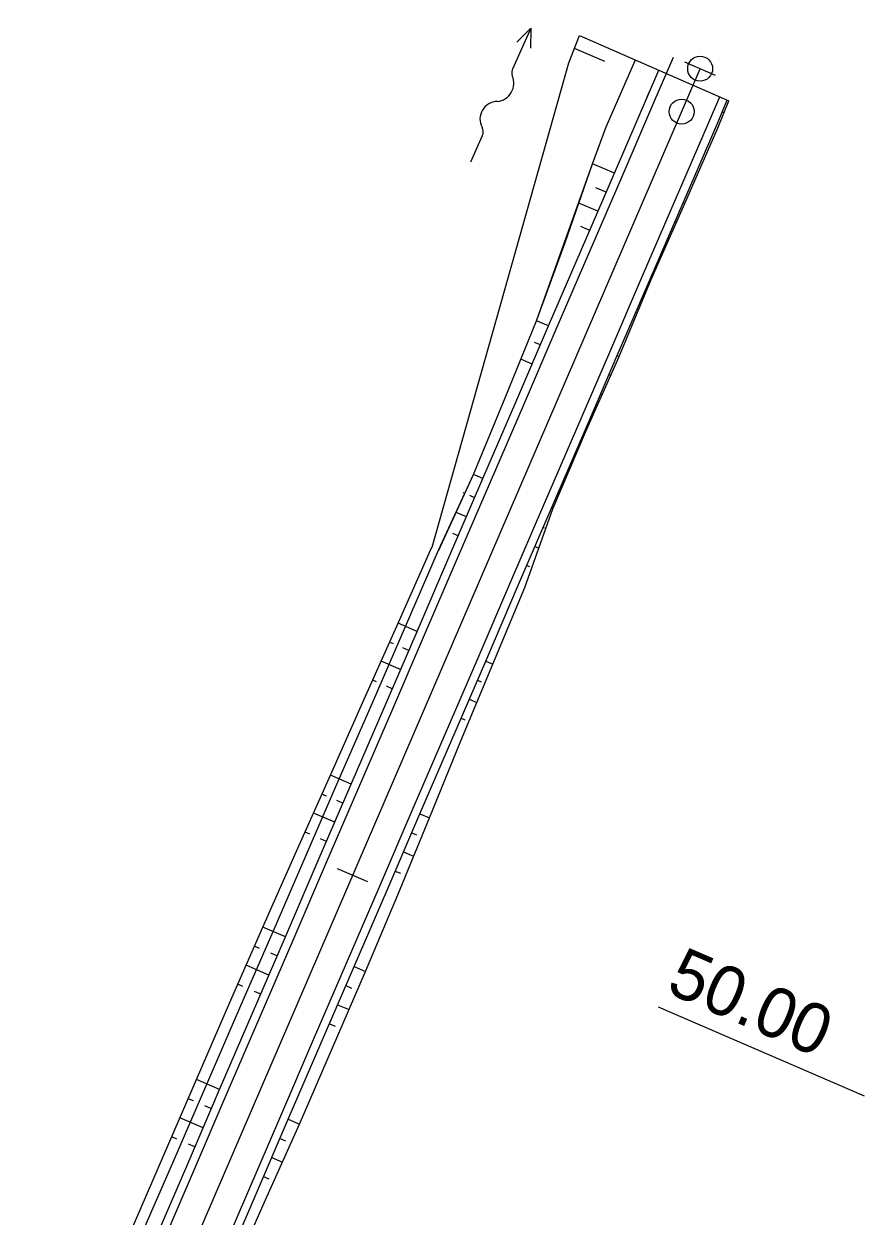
# Model space of a CAD drawing. Extents: x -481656 to -478728, y -1113199 to -1110710.
# Drawn here: x -480117.1 to -480066.6, y -1112436.3 to -1112364.6 of the extents above; entities that cross this region are included whole.
import ezdxf

# ---------------------------------------------------------------- set-up
doc = ezdxf.new("R2010")
doc.units = 0
for name, color, linetype in [('C14_HATCH_SLOPE_L', 7, 'Continuous'), ('C14_HATCH_SLOPE_R', 7, 'Continuous'), ('C14_HECTOMETRY', 7, 'Continuous'), ('C14_HLBODY', 7, 'Continuous'), ('C14_HRANA_TELESO', 7, 'Continuous'), ('C14_KORUNA', 7, 'Continuous'), ('C14_OSA', 7, 'Continuous'), ('C14_PRIKOP', 7, 'Continuous'), ('C14_STANICENI', 7, 'Continuous'), ('C14_VOZOVKA', 7, 'Continuous'), ('C14_ZPEVKRAJ', 7, 'Continuous'), ('DRENÁŽ', 7, 'Continuous'), ('PLYN', 7, 'Continuous')]:
    doc.layers.add(name, color=color, linetype=linetype)

# ---------------------------------------------------------------- blocks, each defined once
blk = doc.blocks.new('A$C70B')
at = {"layer": 'DRENÁŽ'}
for p, q in [((0.869, 0.002), (-0.869, -0.002)), ((6.861, 0.426), (7.971, -0.002)), ((7.971, -0.002), (5.275, -0.002)), ((7.971, -0.002), (6.862, -0.478))]:
    blk.add_line(p, q, dxfattribs=at)
for centre, radius, start, end in [((0.872, 0.584), 0.582, 269.69241, 322.79009), ((2.168, -0.416), 1.055, 24.40393, 142.08362), ((4.08, 0.589), 1.109, 210.88731, 317.37071), ((5.319, -0.636), 0.636, 85.97658, 131.72478)]:
    blk.add_arc(centre, radius, start, end, dxfattribs=at)

msp = doc.modelspace()

# ---------------------------------------------------------------- linework, layer by layer
at = {"layer": 'C14_HATCH_SLOPE_L'}
for p, q in [((-480082.17, -1112366.882), (-480084.006, -1112366.091)), ((-480082.169, -1112366.882), (-480084.005, -1112366.091)), ((-480081.597, -1112373.59), (-480082.906, -1112373.026)), ((-480083.321, -1112374.208), (-480083.321, -1112374.208)), ((-480082.091, -1112374.738), (-480082.706, -1112374.473)), ((-480082.586, -1112375.886), (-480083.735, -1112375.391)), ((-480084.15, -1112376.574), (-480084.15, -1112376.574)), ((-480083.081, -1112377.034), (-480083.616, -1112376.804)), ((-480085.554, -1112382.774), (-480086.281, -1112382.461)), ((-480086.751, -1112383.619), (-480086.751, -1112383.619)), ((-480086.049, -1112383.922), (-480086.4, -1112383.77)), ((-480086.544, -1112385.07), (-480087.222, -1112384.778)), ((-480089.512, -1112391.957), (-480090.068, -1112391.718)), ((-480090.644, -1112392.83), (-480090.694, -1112392.809)), ((-480090.007, -1112393.105), (-480090.301, -1112392.978)), ((-480090.501, -1112394.253), (-480091.12, -1112393.987)), ((-480090.996, -1112395.401), (-480091.321, -1112395.261)), ((-480093.469, -1112401.141), (-480094.609, -1112400.65)), ((-480094.889, -1112401.89), (-480095.117, -1112401.792)), ((-480093.964, -1112402.289), (-480094.312, -1112402.139)), ((-480094.459, -1112403.437), (-480095.626, -1112402.934)), ((-480095.896, -1112404.179), (-480096.134, -1112404.076)), ((-480094.954, -1112404.585), (-480095.306, -1112404.434)), ((-480097.427, -1112410.324), (-480098.678, -1112409.785)), ((-480098.915, -1112411.044), (-480099.187, -1112410.927)), ((-480097.922, -1112411.472), (-480098.282, -1112411.317)), ((-480098.416, -1112412.62), (-480099.695, -1112412.069)), ((-480099.921, -1112413.333), (-480100.203, -1112413.211)), ((-480098.911, -1112413.768), (-480099.275, -1112413.612)), ((-480101.385, -1112419.508), (-480102.746, -1112418.921)), ((-480102.937, -1112420.2), (-480103.249, -1112420.066)), ((-480101.879, -1112420.656), (-480102.252, -1112420.496)), ((-480102.374, -1112421.804), (-480103.751, -1112421.21)), ((-480103.938, -1112422.492), (-480104.254, -1112422.355)), ((-480102.869, -1112422.952), (-480103.245, -1112422.79)), ((-480105.342, -1112428.692), (-480106.733, -1112428.092)), ((-480106.918, -1112429.374), (-480107.229, -1112429.239)), ((-480105.837, -1112429.839), (-480106.222, -1112429.674)), ((-480106.332, -1112430.987), (-480107.726, -1112430.387)), ((-480107.912, -1112431.668), (-480108.222, -1112431.534)), ((-480106.826, -1112432.135), (-480107.214, -1112431.968))]:
    msp.add_line(p, q, dxfattribs=at)
at = {"layer": 'C14_HATCH_SLOPE_R'}
for p, q in [((-480075.116, -1112369.922), (-480075.06, -1112369.946)), ((-480075.004, -1112369.971), (-480075.004, -1112369.971)), ((-480077.464, -1112375.371), (-480077.359, -1112375.417)), ((-480077.959, -1112376.519), (-480077.913, -1112376.539)), ((-480077.867, -1112376.559), (-480077.867, -1112376.559)), ((-480078.453, -1112377.667), (-480078.376, -1112377.701)), ((-480078.948, -1112378.815), (-480078.916, -1112378.829)), ((-480078.884, -1112378.843), (-480078.884, -1112378.843)), ((-480081.422, -1112384.555), (-480081.303, -1112384.606)), ((-480081.916, -1112385.703), (-480081.864, -1112385.725)), ((-480081.813, -1112385.747), (-480081.813, -1112385.747)), ((-480082.411, -1112386.851), (-480082.323, -1112386.888)), ((-480082.906, -1112387.999), (-480082.87, -1112388.014)), ((-480082.834, -1112388.03), (-480082.834, -1112388.03)), ((-480085.379, -1112393.738), (-480085.299, -1112393.773)), ((-480085.874, -1112394.886), (-480085.797, -1112394.92)), ((-480085.72, -1112394.953), (-480085.72, -1112394.953)), ((-480086.369, -1112396.034), (-480086.14, -1112396.133)), ((-480086.863, -1112397.182), (-480086.712, -1112397.248)), ((-480086.561, -1112397.313), (-480086.561, -1112397.313)), ((-480089.337, -1112402.922), (-480088.911, -1112403.106)), ((-480089.832, -1112404.07), (-480089.612, -1112404.165)), ((-480089.391, -1112404.26), (-480089.391, -1112404.26)), ((-480090.326, -1112405.218), (-480089.871, -1112405.414)), ((-480090.821, -1112406.366), (-480090.586, -1112406.467)), ((-480090.351, -1112406.568), (-480090.351, -1112406.568)), ((-480093.294, -1112412.105), (-480092.728, -1112412.35)), ((-480093.789, -1112413.253), (-480093.495, -1112413.38)), ((-480093.202, -1112413.506), (-480093.202, -1112413.506)), ((-480094.284, -1112414.401), (-480093.677, -1112414.663)), ((-480094.779, -1112415.549), (-480094.465, -1112415.684)), ((-480094.151, -1112415.82), (-480094.151, -1112415.82)), ((-480097.252, -1112421.289), (-480096.567, -1112421.584)), ((-480097.747, -1112422.437), (-480097.404, -1112422.584)), ((-480097.061, -1112422.732), (-480097.061, -1112422.732)), ((-480098.242, -1112423.585), (-480097.555, -1112423.881)), ((-480098.736, -1112424.733), (-480098.392, -1112424.881)), ((-480098.049, -1112425.029), (-480098.049, -1112425.029)), ((-480101.21, -1112430.472), (-480100.542, -1112430.76)), ((-480101.704, -1112431.62), (-480101.378, -1112431.761)), ((-480101.052, -1112431.902), (-480101.052, -1112431.902)), ((-480102.199, -1112432.768), (-480101.562, -1112433.043)), ((-480102.694, -1112433.916), (-480102.383, -1112434.05)), ((-480102.072, -1112434.184), (-480102.072, -1112434.184))]:
    msp.add_line(p, q, dxfattribs=at)
at = {"layer": 'C14_HECTOMETRY'}
msp.add_circle((-480077.551, -1112369.889), 0.75, dxfattribs=at)
at = {"layer": 'C14_HLBODY'}
msp.add_circle((-480076.44, -1112367.31), 0.75, dxfattribs=at)
at = {"layer": 'C14_HRANA_TELESO'}
for p, q in [((-480084.346, -1112366.961), (-480083.701, -1112365.308)), ((-480084.345, -1112366.962), (-480083.7, -1112365.308)), ((-480083.7, -1112365.308), (-480074.708, -1112369.248)), ((-480092.564, -1112396.087), (-480084.345, -1112366.962)), ((-480075.357, -1112370.835), (-480074.708, -1112369.248)), ((-480077.359, -1112375.417), (-480075.357, -1112370.835)), ((-480086.281, -1112382.461), (-480082.906, -1112373.026)), ((-480084.564, -1112377.756), (-480082.906, -1112373.026)), ((-480079.392, -1112379.985), (-480077.359, -1112375.417)), ((-480086.281, -1112382.461), (-480084.564, -1112377.756)), ((-480081.303, -1112384.606), (-480079.392, -1112379.985)), ((-480088.162, -1112387.095), (-480086.281, -1112382.461)), ((-480088.162, -1112387.095), (-480086.281, -1112382.461)), ((-480083.344, -1112389.171), (-480081.303, -1112384.606)), ((-480090.068, -1112391.718), (-480088.162, -1112387.095)), ((-480090.068, -1112391.718), (-480088.162, -1112387.095)), ((-480085.299, -1112393.773), (-480083.344, -1112389.171)), ((-480086.981, -1112398.493), (-480085.299, -1112393.773)), ((-480094.609, -1112400.65), (-480092.575, -1112396.082)), ((-480088.911, -1112403.106), (-480086.981, -1112398.493)), ((-480096.643, -1112405.218), (-480094.609, -1112400.65)), ((-480090.832, -1112407.722), (-480088.911, -1112403.106)), ((-480098.678, -1112409.785), (-480096.643, -1112405.218)), ((-480092.728, -1112412.35), (-480090.832, -1112407.722)), ((-480100.712, -1112414.354), (-480098.678, -1112409.785)), ((-480094.625, -1112416.976), (-480092.728, -1112412.35)), ((-480102.746, -1112418.921), (-480100.712, -1112414.354)), ((-480096.567, -1112421.584), (-480094.625, -1112416.976)), ((-480104.756, -1112423.499), (-480102.746, -1112418.921)), ((-480098.543, -1112426.177), (-480096.567, -1112421.584)), ((-480106.733, -1112428.092), (-480104.756, -1112423.499)), ((-480100.542, -1112430.76), (-480098.543, -1112426.177)), ((-480108.719, -1112432.681), (-480106.733, -1112428.092)), ((-480102.582, -1112435.326), (-480100.542, -1112430.76)), ((-480110.705, -1112437.27), (-480108.719, -1112432.681)), ((-480104.622, -1112439.891), (-480102.582, -1112435.326))]:
    msp.add_line(p, q, dxfattribs=at)
at = {"layer": 'C14_KORUNA'}
for p, q in [((-480081.597, -1112373.59), (-480078.928, -1112367.399)), ((-480079.618, -1112368.999), (-480079.486, -1112368.692)), ((-480075.485, -1112370.78), (-480074.806, -1112369.204)), ((-480077.464, -1112375.371), (-480075.485, -1112370.78)), ((-480083.575, -1112378.182), (-480081.597, -1112373.59)), ((-480079.443, -1112379.963), (-480077.464, -1112375.371)), ((-480085.554, -1112382.774), (-480083.575, -1112378.182)), ((-480081.422, -1112384.555), (-480079.443, -1112379.963)), ((-480087.533, -1112387.366), (-480085.554, -1112382.774)), ((-480083.4, -1112389.147), (-480081.422, -1112384.555)), ((-480089.512, -1112391.957), (-480087.533, -1112387.366)), ((-480085.379, -1112393.738), (-480083.4, -1112389.147)), ((-480091.491, -1112396.549), (-480089.512, -1112391.957)), ((-480087.358, -1112398.33), (-480085.379, -1112393.738)), ((-480093.469, -1112401.141), (-480091.491, -1112396.549)), ((-480089.337, -1112402.922), (-480087.358, -1112398.33)), ((-480095.448, -1112405.733), (-480093.469, -1112401.141)), ((-480091.316, -1112407.514), (-480089.337, -1112402.922)), ((-480097.427, -1112410.324), (-480095.448, -1112405.733)), ((-480093.294, -1112412.105), (-480091.316, -1112407.514)), ((-480099.406, -1112414.916), (-480097.427, -1112410.324)), ((-480095.273, -1112416.697), (-480093.294, -1112412.105)), ((-480101.385, -1112419.508), (-480099.406, -1112414.916)), ((-480097.252, -1112421.289), (-480095.273, -1112416.697)), ((-480103.364, -1112424.1), (-480101.385, -1112419.508)), ((-480099.231, -1112425.881), (-480097.252, -1112421.289)), ((-480105.342, -1112428.692), (-480103.364, -1112424.1)), ((-480101.21, -1112430.472), (-480099.231, -1112425.881)), ((-480107.321, -1112433.283), (-480105.342, -1112428.692)), ((-480103.189, -1112435.064), (-480101.21, -1112430.472)), ((-480109.3, -1112437.875), (-480107.321, -1112433.283)), ((-480105.167, -1112439.656), (-480103.189, -1112435.064))]:
    msp.add_line(p, q, dxfattribs=at)
at = {"layer": 'C14_OSA'}
msp.add_line((-480117.117, -1112461.699), (-480076.44, -1112367.31), dxfattribs=at)
at = {"layer": 'C14_PRIKOP'}
for p, q in [((-480082.089, -1112370.811), (-480080.326, -1112366.786)), ((-480082.906, -1112373.026), (-480082.089, -1112370.811)), ((-480092.172, -1112396.255), (-480090.068, -1112391.718)), ((-480092.165, -1112396.258), (-480090.068, -1112391.718)), ((-480094.163, -1112400.842), (-480092.172, -1112396.255)), ((-480096.154, -1112405.428), (-480094.163, -1112400.842)), ((-480098.145, -1112410.015), (-480096.154, -1112405.428)), ((-480100.136, -1112414.601), (-480098.145, -1112410.015)), ((-480102.127, -1112419.188), (-480100.136, -1112414.601)), ((-480104.118, -1112423.775), (-480102.127, -1112419.188)), ((-480106.109, -1112428.361), (-480104.118, -1112423.775)), ((-480108.1, -1112432.948), (-480106.109, -1112428.361)), ((-480110.091, -1112437.534), (-480108.1, -1112432.948))]:
    msp.add_line(p, q, dxfattribs=at)
at = {"layer": 'C14_STANICENI'}
for p, q in [((-480075.525, -1112367.713), (-480077.362, -1112366.922)), ((-480096.421, -1112416.202), (-480098.258, -1112415.411)), ((-480078.973, -1112423.722), (-480066.575, -1112429.065))]:
    msp.add_line(p, q, dxfattribs=at)
at = {"layer": 'C14_VOZOVKA'}
for p, q in [((-480079.159, -1112369.196), (-480078.05, -1112366.625)), ((-480081.137, -1112373.788), (-480079.159, -1112369.196)), ((-480075.944, -1112370.582), (-480075.264, -1112369.004)), ((-480077.923, -1112375.173), (-480075.944, -1112370.582)), ((-480083.116, -1112378.38), (-480081.137, -1112373.788)), ((-480079.902, -1112379.765), (-480077.923, -1112375.173)), ((-480085.095, -1112382.972), (-480083.116, -1112378.38)), ((-480081.881, -1112384.357), (-480079.902, -1112379.765)), ((-480087.074, -1112387.564), (-480085.095, -1112382.972)), ((-480083.86, -1112388.949), (-480081.881, -1112384.357)), ((-480089.053, -1112392.155), (-480087.074, -1112387.564)), ((-480085.838, -1112393.54), (-480083.86, -1112388.949)), ((-480091.031, -1112396.747), (-480089.053, -1112392.155)), ((-480087.817, -1112398.132), (-480085.838, -1112393.54)), ((-480093.01, -1112401.339), (-480091.031, -1112396.747)), ((-480089.796, -1112402.724), (-480087.817, -1112398.132)), ((-480094.989, -1112405.931), (-480093.01, -1112401.339)), ((-480091.775, -1112407.316), (-480089.796, -1112402.724)), ((-480096.968, -1112410.522), (-480094.989, -1112405.931)), ((-480093.754, -1112411.908), (-480091.775, -1112407.316)), ((-480098.947, -1112415.114), (-480096.968, -1112410.522)), ((-480095.732, -1112416.499), (-480093.754, -1112411.908)), ((-480100.926, -1112419.706), (-480098.947, -1112415.114)), ((-480097.711, -1112421.091), (-480095.732, -1112416.499)), ((-480102.904, -1112424.298), (-480100.926, -1112419.706)), ((-480099.69, -1112425.683), (-480097.711, -1112421.091)), ((-480104.883, -1112428.889), (-480102.904, -1112424.298)), ((-480101.669, -1112430.275), (-480099.69, -1112425.683)), ((-480106.862, -1112433.481), (-480104.883, -1112428.889)), ((-480103.648, -1112434.866), (-480101.669, -1112430.275)), ((-480108.841, -1112438.073), (-480106.862, -1112433.481)), ((-480105.627, -1112439.458), (-480103.648, -1112434.866))]:
    msp.add_line(p, q, dxfattribs=at)
at = {"layer": 'C14_ZPEVKRAJ'}
for p, q in [((-480079.159, -1112369.196), (-480078.05, -1112366.625)), ((-480081.137, -1112373.788), (-480079.159, -1112369.196)), ((-480075.944, -1112370.582), (-480075.264, -1112369.004)), ((-480077.923, -1112375.173), (-480075.944, -1112370.582)), ((-480083.116, -1112378.38), (-480081.137, -1112373.788)), ((-480079.902, -1112379.765), (-480077.923, -1112375.173)), ((-480085.095, -1112382.972), (-480083.116, -1112378.38)), ((-480081.881, -1112384.357), (-480079.902, -1112379.765)), ((-480087.074, -1112387.564), (-480085.095, -1112382.972)), ((-480083.86, -1112388.949), (-480081.881, -1112384.357)), ((-480089.053, -1112392.155), (-480087.074, -1112387.564)), ((-480085.838, -1112393.54), (-480083.86, -1112388.949)), ((-480091.031, -1112396.747), (-480089.053, -1112392.155)), ((-480087.817, -1112398.132), (-480085.838, -1112393.54)), ((-480093.01, -1112401.339), (-480091.031, -1112396.747)), ((-480089.796, -1112402.724), (-480087.817, -1112398.132)), ((-480094.989, -1112405.931), (-480093.01, -1112401.339)), ((-480091.775, -1112407.316), (-480089.796, -1112402.724)), ((-480096.968, -1112410.522), (-480094.989, -1112405.931)), ((-480093.754, -1112411.908), (-480091.775, -1112407.316)), ((-480098.947, -1112415.114), (-480096.968, -1112410.522)), ((-480095.732, -1112416.499), (-480093.754, -1112411.908)), ((-480100.926, -1112419.706), (-480098.947, -1112415.114)), ((-480097.711, -1112421.091), (-480095.732, -1112416.499)), ((-480102.904, -1112424.298), (-480100.926, -1112419.706)), ((-480099.69, -1112425.683), (-480097.711, -1112421.091)), ((-480104.883, -1112428.889), (-480102.904, -1112424.298)), ((-480101.669, -1112430.275), (-480099.69, -1112425.683)), ((-480106.862, -1112433.481), (-480104.883, -1112428.889)), ((-480103.648, -1112434.866), (-480101.669, -1112430.275)), ((-480108.841, -1112438.073), (-480106.862, -1112433.481)), ((-480105.627, -1112439.458), (-480103.648, -1112434.866))]:
    msp.add_line(p, q, dxfattribs=at)

# ---------------------------------------------------------------- block references
at = {"layer": 'PLYN', "rotation": 65.74340576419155}
msp.add_blockref('A$C70B', (-480089.897, -1112372.145), dxfattribs=at)

# ---------------------------------------------------------------- texts
at = {"layer": 'C14_STANICENI'}
msp.add_text('50.00', height=3, rotation=336.68644, dxfattribs=at).set_placement((-480078.578, -1112422.803))

doc.saveas('drawing.dxf')
